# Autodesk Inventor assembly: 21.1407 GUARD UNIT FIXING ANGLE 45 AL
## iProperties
Created: 2007-01
Part Number: 21.1407 GUARD UNIT FIXING ANGLE 45 AL
Document SubType Name: Assembly
Designer: Andy Moles
Author: Andy Moles
